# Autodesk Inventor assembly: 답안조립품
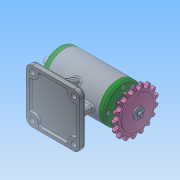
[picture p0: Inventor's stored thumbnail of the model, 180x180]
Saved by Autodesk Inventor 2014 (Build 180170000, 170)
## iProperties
Created: 2019-06
Part Number: 답안조립품
Document SubType Name: Assembly
Designer: net
Author: net
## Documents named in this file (11)
- C:\Users\net\Desktop\490604V1033\답안조립품.iam
- C:\Users\net\Desktop\490604V1033\본체.ipt
- C:\Users\net\Desktop\490604V1033\베어링 6203.ipt
- C:\Users\net\Desktop\490604V1033\축.ipt
- C:\Users\net\Desktop\490604V1033\커버.ipt
- C:\Users\net\Desktop\490604V1033\오일 실 17 30 5.ipt
- C:\Users\net\Desktop\490604V1033\볼트 M4.ipt
- C:\Users\net\Desktop\490604V1033\키 4x4x12.ipt
- C:\Users\net\Desktop\490604V1033\스프로킷.ipt
- C:\Users\net\Desktop\490604V1033\평와셔.ipt
- C:\Users\net\Desktop\490604V1033\스프링와셔.ipt
